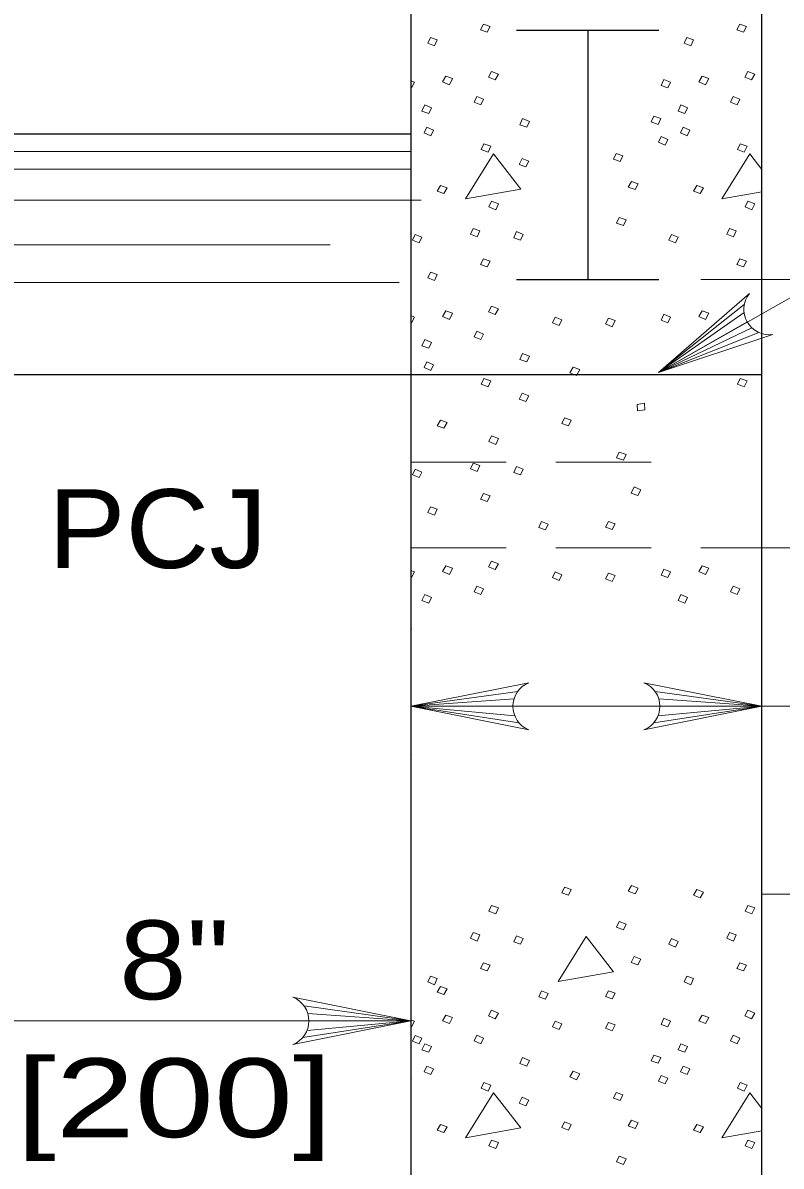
# Model space of a CAD drawing. Extents: x -1431.2 to -1397.2, y -1045.1 to -1001.1.
# Drawn here: x -1422.139 to -1420.61, y -1041.7 to -1039.396 of the extents above; entities that cross this region are included whole.
import ezdxf
from ezdxf.enums import TextEntityAlignment as Align

# ---------------------------------------------------------------- set-up
doc = ezdxf.new("R2010")
doc.units = 0
doc.header["$LTSCALE"] = 0.064
doc.linetypes.add('MEDIUM_DASHED', pattern=[4.5, 3, -1.5])
doc.layers.add('1', color=7, linetype='Continuous', lineweight=13)

msp = doc.modelspace()

# ---------------------------------------------------------------- linework, layer by layer
at = {"layer": '1', "lineweight": 25}
for p, q in [((-1420.649, -1043.61933), (-1420.649, -1038.68067)), ((-1421.35642, -1038.98608), (-1421.35642, -1040.11325)), ((-1421.1435, -1039.41017), (-1420.85692, -1039.41017)), ((-1421.00017, -1039.41017), (-1421.00017, -1039.91325)), ((-1422.38333, -1039.61925), (-1421.35642, -1039.61925)), ((-1421.1435, -1039.91325), (-1420.85692, -1039.91325)), ((-1421.35642, -1040.10408), (-1421.35642, -1042.24275))]:
    msp.add_line(p, q, dxfattribs=at)
at = {"layer": '1'}
for p, q in [((-1422.38333, -1039.65508), (-1421.61217, -1039.65508)), ((-1421.54975, -1039.65508), (-1421.7975, -1039.65508)), ((-1421.71883, -1039.65508), (-1421.35642, -1039.65508)), ((-1420.649, -1039.69142), (-1420.67358, -1039.65983)), ((-1422.24483, -1039.69092), (-1421.98408, -1039.69092)), ((-1421.79125, -1039.69092), (-1422.1705, -1039.69092)), ((-1421.97225, -1039.69092), (-1421.35642, -1039.69092)), ((-1422.28817, -1039.75308), (-1421.52967, -1039.75308)), ((-1421.33575, -1039.75308), (-1421.87775, -1039.75308)), ((-1421.71658, -1039.75308), (-1421.35642, -1039.75308)), ((-1422.23358, -1039.84283), (-1421.99242, -1039.84283)), ((-1421.75308, -1039.84283), (-1422.18017, -1039.84283)), ((-1421.8625, -1039.84283), (-1421.51908, -1039.84283)), ((-1421.37983, -1039.91908), (-1422.25742, -1039.91908)), ((-1422.01417, -1039.91908), (-1421.77283, -1039.91908)), ((-1421.71658, -1039.91908), (-1421.49108, -1039.91908)), ((-1420.77192, -1039.91325), (-1415.55833, -1039.91325)), ((-1420.68458, -1039.9635), (-1420.85742, -1040.10017)), ((-1420.68483, -1039.97967), (-1420.85742, -1040.10017)), ((-1420.67858, -1039.99842), (-1420.85742, -1040.10017)), ((-1420.66917, -1040.0105), (-1420.85742, -1040.10017)), ((-1420.65542, -1040.01983), (-1420.85742, -1040.10017)), ((-1420.734, -1040.10408), (-1421.74733, -1040.10408)), ((-1421.14117, -1040.74292), (-1421.35642, -1040.773)), ((-1421.14842, -1040.75775), (-1421.35642, -1040.773)), ((-1420.86425, -1040.74292), (-1420.649, -1040.773)), ((-1420.857, -1040.75775), (-1420.649, -1040.773)), ((-1421.35642, -1040.773), (-1419.82525, -1040.773)), ((-1421.15067, -1040.773), (-1421.35642, -1040.773)), ((-1421.14683, -1040.79233), (-1421.35642, -1040.773)), ((-1421.13867, -1040.80625), (-1421.35642, -1040.773)), ((-1420.86683, -1040.80625), (-1420.649, -1040.773)), ((-1420.85858, -1040.79233), (-1420.649, -1040.773)), ((-1420.85475, -1040.773), (-1420.649, -1040.773)), ((-1419.9465, -1041.15183), (-1420.649, -1041.15183)), ((-1421.57158, -1041.37675), (-1421.35642, -1041.40692)), ((-1421.56433, -1041.39167), (-1421.35642, -1041.40692)), ((-1421.57417, -1041.44017), (-1421.35642, -1041.40692)), ((-1421.56592, -1041.42625), (-1421.35642, -1041.40692)), ((-1421.56208, -1041.40692), (-1421.35642, -1041.40692)), ((-1420.649, -1041.58333), (-1420.67358, -1041.55175))]:
    msp.add_line(p, q, dxfattribs=at)
at = {"layer": '1', "linetype": 'MEDIUM_DASHED'}
for p, q in [((-1421.35642, -1040.28092), (-1420.856, -1040.28092)), ((-1421.35642, -1040.45358), (-1419.54317, -1040.45358))]:
    msp.add_line(p, q, dxfattribs=at)
at = {"layer": '1'}
for points in [[(-1421.21008, -1039.39808), (-1421.19642, -1039.40292), (-1421.20283, -1039.41433), (-1421.21642, -1039.4095)], [(-1420.6935, -1039.39808), (-1420.67992, -1039.40292), (-1420.68625, -1039.41433), (-1420.69983, -1039.4095)], [(-1421.317, -1039.425), (-1421.30342, -1039.42983), (-1421.30883, -1039.44208), (-1421.32242, -1039.43642)], [(-1420.80042, -1039.425), (-1420.78683, -1039.42983), (-1420.79233, -1039.44208), (-1420.80592, -1039.43642)], [(-1421.19375, -1039.4935), (-1421.18017, -1039.49917), (-1421.1865, -1039.51058), (-1421.20008, -1039.50492)], [(-1420.67725, -1039.4935), (-1420.66358, -1039.49917), (-1420.67, -1039.51058), (-1420.68358, -1039.50492)], [(-1421.28617, -1039.50325), (-1421.27258, -1039.50817), (-1421.27892, -1039.52042), (-1421.2925, -1039.51467)], [(-1420.84667, -1039.50975), (-1420.83308, -1039.5155), (-1420.8385, -1039.52692), (-1420.85208, -1039.522)], [(-1420.76967, -1039.50325), (-1420.75608, -1039.50817), (-1420.76242, -1039.52042), (-1420.776, -1039.51467)], [(-1421.32875, -1039.56117), (-1421.31517, -1039.56683), (-1421.32058, -1039.57825), (-1421.33417, -1039.57342)], [(-1421.22367, -1039.544), (-1421.21008, -1039.54975), (-1421.2155, -1039.56117), (-1421.22908, -1039.55542)], [(-1420.81225, -1039.56117), (-1420.79867, -1039.56683), (-1420.80408, -1039.57825), (-1420.81767, -1039.57342)], [(-1420.70708, -1039.544), (-1420.6935, -1039.54975), (-1420.699, -1039.56117), (-1420.71258, -1039.55542)], [(-1420.86658, -1039.584), (-1420.853, -1039.58883), (-1420.85842, -1039.60033), (-1420.872, -1039.59542)], [(-1421.32425, -1039.606), (-1421.31067, -1039.61175), (-1421.31608, -1039.62317), (-1421.32967, -1039.61742)], [(-1421.13125, -1039.58883), (-1421.11758, -1039.59458), (-1421.12308, -1039.606), (-1421.13667, -1039.60108)], [(-1420.80767, -1039.606), (-1420.79408, -1039.61175), (-1420.79958, -1039.62317), (-1420.81317, -1039.61742)], [(-1420.85208, -1039.62475), (-1420.8385, -1039.6305), (-1420.844, -1039.64192), (-1420.85758, -1039.63617)], [(-1421.20917, -1039.63942), (-1421.19558, -1039.64433), (-1421.201, -1039.65658), (-1421.21458, -1039.65083)], [(-1420.69258, -1039.63942), (-1420.679, -1039.64433), (-1420.6845, -1039.65658), (-1420.69808, -1039.65083)], [(-1421.19008, -1039.65983), (-1421.24633, -1039.75033), (-1421.13483, -1039.73075)], [(-1421.13208, -1039.66883), (-1421.1185, -1039.6745), (-1421.12483, -1039.68592), (-1421.1385, -1039.681)], [(-1420.94275, -1039.659), (-1420.92917, -1039.66392), (-1420.93458, -1039.67533), (-1420.94817, -1039.67042)], [(-1421.29708, -1039.72342), (-1421.28342, -1039.72833), (-1421.28983, -1039.73975), (-1421.30342, -1039.73483)], [(-1420.91192, -1039.71525), (-1420.89833, -1039.72017), (-1420.90467, -1039.73158), (-1420.91825, -1039.72667)], [(-1420.7805, -1039.72342), (-1420.76692, -1039.72833), (-1420.77325, -1039.73975), (-1420.78683, -1039.73483)], [(-1421.19375, -1039.75525), (-1421.18017, -1039.76017), (-1421.18558, -1039.77233), (-1421.19917, -1039.76667)], [(-1420.67725, -1039.75525), (-1420.66358, -1039.76017), (-1420.66908, -1039.77233), (-1420.68267, -1039.76667)], [(-1420.93642, -1039.78783), (-1420.92275, -1039.79275), (-1420.92825, -1039.80417), (-1420.94183, -1039.79925)], [(-1421.23092, -1039.80983), (-1421.21733, -1039.81475), (-1421.22275, -1039.827), (-1421.23633, -1039.82133)], [(-1421.14392, -1039.81642), (-1421.13033, -1039.82208), (-1421.13575, -1039.8335), (-1421.14933, -1039.82867)], [(-1420.71433, -1039.80983), (-1420.70075, -1039.81475), (-1420.70625, -1039.827), (-1420.71983, -1039.82133)], [(-1421.34783, -1039.82208), (-1421.33417, -1039.82783), (-1421.33967, -1039.83925), (-1421.35325, -1039.8335)], [(-1420.83125, -1039.82208), (-1420.81767, -1039.82783), (-1420.82308, -1039.83925), (-1420.83667, -1039.8335)], [(-1421.21008, -1039.871), (-1421.19642, -1039.87592), (-1421.20283, -1039.88733), (-1421.21642, -1039.88242)], [(-1420.6935, -1039.871), (-1420.67992, -1039.87592), (-1420.68625, -1039.88733), (-1420.69983, -1039.88242)], [(-1421.317, -1039.89792), (-1421.30342, -1039.90283), (-1421.30883, -1039.91508), (-1421.32242, -1039.90933)], [(-1421.28617, -1039.97625), (-1421.27258, -1039.98108), (-1421.27892, -1039.99333), (-1421.2925, -1039.98767)], [(-1421.19375, -1039.96642), (-1421.18017, -1039.97217), (-1421.1865, -1039.98358), (-1421.20008, -1039.97783)], [(-1420.76967, -1039.97625), (-1420.75608, -1039.98108), (-1420.76242, -1039.99333), (-1420.776, -1039.98767)], [(-1421.066, -1039.9885), (-1421.05242, -1039.99417), (-1421.05783, -1040.00558), (-1421.07142, -1039.99992)], [(-1420.95817, -1039.99092), (-1420.94458, -1039.99583), (-1420.95092, -1040.008), (-1420.9645, -1040.00233)], [(-1420.84667, -1039.98275), (-1420.83308, -1039.9885), (-1420.8385, -1039.99992), (-1420.85208, -1039.995)], [(-1421.22367, -1040.017), (-1421.21008, -1040.02275), (-1421.2155, -1040.03408), (-1421.22908, -1040.02842)], [(-1421.32875, -1040.03408), (-1421.31517, -1040.03983), (-1421.32058, -1040.05125), (-1421.33417, -1040.04633)], [(-1421.13125, -1040.06183), (-1421.11758, -1040.06758), (-1421.12308, -1040.079), (-1421.13667, -1040.07408)], [(-1421.32425, -1040.079), (-1421.31067, -1040.08467), (-1421.31608, -1040.09608), (-1421.32967, -1040.09042)], [(-1421.02975, -1040.08958), (-1421.01617, -1040.0945), (-1421.0225, -1040.10667), (-1421.03608, -1040.101)], [(-1421.20917, -1040.11242), (-1421.19558, -1040.11733), (-1421.201, -1040.1295), (-1421.21458, -1040.12383)], [(-1420.69258, -1040.11242), (-1420.679, -1040.11733), (-1420.6845, -1040.1295), (-1420.69808, -1040.12383)], [(-1421.13208, -1040.14175), (-1421.1185, -1040.1475), (-1421.12483, -1040.15892), (-1421.1385, -1040.154)], [(-1420.885, -1040.17525), (-1420.89958, -1040.17775), (-1420.90033, -1040.16467), (-1420.88583, -1040.16217)], [(-1421.29708, -1040.19642), (-1421.28342, -1040.20133), (-1421.28983, -1040.21275), (-1421.30342, -1040.20783)], [(-1421.04692, -1040.1915), (-1421.03333, -1040.19642), (-1421.03875, -1040.20783), (-1421.05242, -1040.20292)], [(-1421.19375, -1040.22817), (-1421.18017, -1040.23308), (-1421.18558, -1040.24533), (-1421.19917, -1040.23967)], [(-1420.93642, -1040.26083), (-1420.92275, -1040.26575), (-1420.92825, -1040.27717), (-1420.94183, -1040.27225)], [(-1421.34783, -1040.29508), (-1421.33417, -1040.30083), (-1421.33967, -1040.31217), (-1421.35325, -1040.3065)], [(-1421.23092, -1040.28283), (-1421.21733, -1040.28775), (-1421.22275, -1040.3), (-1421.23633, -1040.29425)], [(-1421.14392, -1040.28942), (-1421.13033, -1040.29508), (-1421.13575, -1040.3065), (-1421.14933, -1040.30158)], [(-1421.21008, -1040.344), (-1421.19642, -1040.34892), (-1421.20283, -1040.36033), (-1421.21642, -1040.35542)], [(-1420.9065, -1040.331), (-1420.89292, -1040.33667), (-1420.89925, -1040.34808), (-1420.91283, -1040.34317)], [(-1421.317, -1040.37092), (-1421.30342, -1040.37583), (-1421.30883, -1040.38808), (-1421.32242, -1040.38233)], [(-1421.09317, -1040.40025), (-1421.07958, -1040.406), (-1421.085, -1040.41742), (-1421.09858, -1040.4125)], [(-1420.95817, -1040.40025), (-1420.94458, -1040.40517), (-1420.95092, -1040.41658), (-1420.9645, -1040.41167)], [(-1421.19375, -1040.48017), (-1421.18017, -1040.48592), (-1421.1865, -1040.49733), (-1421.20008, -1040.49158)], [(-1421.28617, -1040.48992), (-1421.27258, -1040.49483), (-1421.27892, -1040.50708), (-1421.2925, -1040.50142)], [(-1421.066, -1040.50217), (-1421.05242, -1040.50792), (-1421.05783, -1040.51933), (-1421.07142, -1040.51358)], [(-1420.95817, -1040.50467), (-1420.94458, -1040.5095), (-1420.95092, -1040.52175), (-1420.9645, -1040.51608)], [(-1420.84667, -1040.4965), (-1420.83308, -1040.50217), (-1420.8385, -1040.51358), (-1420.85208, -1040.50875)], [(-1420.76967, -1040.48992), (-1420.75608, -1040.49483), (-1420.76242, -1040.50708), (-1420.776, -1040.50142)], [(-1421.22367, -1040.53075), (-1421.21008, -1040.53642), (-1421.2155, -1040.54783), (-1421.22908, -1040.54217)], [(-1420.70708, -1040.53075), (-1420.6935, -1040.53642), (-1420.699, -1040.54783), (-1420.71258, -1040.54217)], [(-1421.32875, -1040.54783), (-1421.31517, -1040.55358), (-1421.32058, -1040.565), (-1421.33417, -1040.56008)], [(-1420.81225, -1040.54783), (-1420.79867, -1040.55358), (-1420.80408, -1040.565), (-1420.81767, -1040.56008)], [(-1421.04692, -1041.1375), (-1421.03333, -1041.14233), (-1421.03875, -1041.15375), (-1421.05242, -1041.14892)], [(-1420.91192, -1041.13425), (-1420.89833, -1041.13908), (-1420.90467, -1041.1505), (-1420.91825, -1041.14567)], [(-1420.7805, -1041.14233), (-1420.76692, -1041.14725), (-1420.77325, -1041.15867), (-1420.78683, -1041.15375)], [(-1421.19375, -1041.17417), (-1421.18017, -1041.17908), (-1421.18558, -1041.19133), (-1421.19917, -1041.18558)], [(-1420.67725, -1041.17417), (-1420.66358, -1041.17908), (-1420.66908, -1041.19133), (-1420.68267, -1041.18558)], [(-1420.93642, -1041.20675), (-1420.92275, -1041.21167), (-1420.92825, -1041.22308), (-1420.94183, -1041.21817)], [(-1421.23092, -1041.22883), (-1421.21733, -1041.23367), (-1421.22275, -1041.24592), (-1421.23633, -1041.24025)], [(-1421.14392, -1041.23533), (-1421.13033, -1041.241), (-1421.13575, -1041.25242), (-1421.14933, -1041.24758)], [(-1421.00342, -1041.237), (-1421.05967, -1041.3275), (-1420.94817, -1041.30792)], [(-1420.83125, -1041.241), (-1420.81767, -1041.24675), (-1420.82308, -1041.25817), (-1420.83667, -1041.25242)], [(-1420.71433, -1041.22883), (-1420.70075, -1041.23367), (-1420.70625, -1041.24592), (-1420.71983, -1041.24025)], [(-1421.21008, -1041.29), (-1421.19642, -1041.29483), (-1421.20283, -1041.30625), (-1421.21642, -1041.30142)], [(-1420.9065, -1041.27692), (-1420.89292, -1041.28267), (-1420.89925, -1041.29408), (-1420.91283, -1041.28917)], [(-1420.6935, -1041.29), (-1420.67992, -1041.29483), (-1420.68625, -1041.30625), (-1420.69983, -1041.30142)], [(-1421.317, -1041.31692), (-1421.30342, -1041.32175), (-1421.30883, -1041.334), (-1421.32242, -1041.32833)], [(-1421.29708, -1041.33742), (-1421.28342, -1041.34233), (-1421.28983, -1041.35375), (-1421.30342, -1041.34883)], [(-1420.80042, -1041.31692), (-1420.78683, -1041.32175), (-1420.79233, -1041.334), (-1420.80592, -1041.32833)], [(-1421.09317, -1041.34625), (-1421.07958, -1041.35192), (-1421.085, -1041.36333), (-1421.09858, -1041.3585)], [(-1420.95817, -1041.34625), (-1420.94458, -1041.35108), (-1420.95092, -1041.36258), (-1420.9645, -1041.35767)], [(-1421.28617, -1041.39517), (-1421.27258, -1041.40008), (-1421.27892, -1041.41225), (-1421.2925, -1041.40658)], [(-1421.19375, -1041.38542), (-1421.18017, -1041.39108), (-1421.1865, -1041.4025), (-1421.20008, -1041.39683)], [(-1420.84667, -1041.40167), (-1420.83308, -1041.40742), (-1420.8385, -1041.41883), (-1420.85208, -1041.41392)], [(-1420.76967, -1041.39517), (-1420.75608, -1041.40008), (-1420.76242, -1041.41225), (-1420.776, -1041.40658)], [(-1420.67725, -1041.38542), (-1420.66358, -1041.39108), (-1420.67, -1041.4025), (-1420.68358, -1041.39683)], [(-1421.066, -1041.40742), (-1421.05242, -1041.41308), (-1421.05783, -1041.4245), (-1421.07142, -1041.41883)], [(-1420.95817, -1041.40983), (-1420.94458, -1041.41475), (-1420.95092, -1041.427), (-1420.9645, -1041.42125)], [(-1421.34783, -1041.43608), (-1421.33417, -1041.44183), (-1421.33967, -1041.45325), (-1421.35325, -1041.4475)], [(-1421.22367, -1041.43592), (-1421.21008, -1041.44167), (-1421.2155, -1041.45308), (-1421.22908, -1041.44733)], [(-1420.70708, -1041.43592), (-1420.6935, -1041.44167), (-1420.699, -1041.45308), (-1420.71258, -1041.44733)], [(-1421.32875, -1041.45308), (-1421.31517, -1041.45875), (-1421.32058, -1041.47017), (-1421.33417, -1041.46533)], [(-1420.86658, -1041.47592), (-1420.853, -1041.48075), (-1420.85842, -1041.49217), (-1420.872, -1041.48733)], [(-1420.81225, -1041.45308), (-1420.79867, -1041.45875), (-1420.80408, -1041.47017), (-1420.81767, -1041.46533)], [(-1421.32425, -1041.49792), (-1421.31067, -1041.50358), (-1421.31608, -1041.515), (-1421.32967, -1041.50933)], [(-1421.13125, -1041.48075), (-1421.11758, -1041.4865), (-1421.12308, -1041.49792), (-1421.13667, -1041.493)], [(-1420.80767, -1041.49792), (-1420.79408, -1041.50358), (-1420.79958, -1041.515), (-1420.81317, -1041.50933)], [(-1421.02975, -1041.5085), (-1421.01617, -1041.51342), (-1421.0225, -1041.52567), (-1421.03608, -1041.51992)], [(-1420.85208, -1041.51667), (-1420.8385, -1041.52242), (-1420.844, -1041.53383), (-1420.85758, -1041.52808)], [(-1421.20917, -1041.53133), (-1421.19558, -1041.53625), (-1421.201, -1041.5485), (-1421.21458, -1041.54275)], [(-1420.69258, -1041.53133), (-1420.679, -1041.53625), (-1420.6845, -1041.5485), (-1420.69808, -1041.54275)], [(-1421.19008, -1041.55175), (-1421.24633, -1041.64225), (-1421.13483, -1041.62267)], [(-1421.13208, -1041.56067), (-1421.1185, -1041.56642), (-1421.12483, -1041.57783), (-1421.1385, -1041.57292)], [(-1420.94275, -1041.55092), (-1420.92917, -1041.55583), (-1420.93458, -1041.56725), (-1420.94817, -1041.56233)], [(-1421.04692, -1041.61042), (-1421.03333, -1041.61533), (-1421.03875, -1041.62675), (-1421.05242, -1041.62183)], [(-1420.91192, -1041.60717), (-1420.89833, -1041.61208), (-1420.90467, -1041.6235), (-1420.91825, -1041.61858)], [(-1421.29708, -1041.61533), (-1421.28342, -1041.62025), (-1421.28983, -1041.63167), (-1421.30342, -1041.62675)], [(-1420.7805, -1041.61533), (-1420.76692, -1041.62025), (-1420.77325, -1041.63167), (-1420.78683, -1041.62675)], [(-1421.19375, -1041.64717), (-1421.18017, -1041.652), (-1421.18558, -1041.66425), (-1421.19917, -1041.65858)], [(-1420.67725, -1041.64717), (-1420.66358, -1041.652), (-1420.66908, -1041.66425), (-1420.68267, -1041.65858)], [(-1420.93642, -1041.67975), (-1420.92275, -1041.68467), (-1420.92825, -1041.69608), (-1420.94183, -1041.69117)]]:
    msp.add_lwpolyline(points, close=True, dxfattribs=at)
for points in [[(-1421.35642, -1039.51267), (-1421.34958, -1039.5155), (-1421.355, -1039.52692), (-1421.35642, -1039.52642)], [(-1421.35642, -1039.62992), (-1421.355, -1039.6305), (-1421.35642, -1039.63333)], [(-1420.67358, -1039.65983), (-1420.72975, -1039.75033), (-1420.649, -1039.73617)], [(-1420.85742, -1040.10017), (-1420.16867, -1039.71008), (-1419.82525, -1039.71008)], [(-1420.67425, -1039.94125), (-1420.85742, -1040.10017), (-1420.62725, -1040.02383)], [(-1421.35642, -1039.98558), (-1421.34958, -1039.9885), (-1421.355, -1039.99992), (-1421.35642, -1039.99942)], [(-1421.35642, -1040.10292), (-1421.355, -1040.10342), (-1421.35642, -1040.10633)], [(-1421.35642, -1040.49933), (-1421.34958, -1040.50217), (-1421.355, -1040.51358), (-1421.35642, -1040.51308)], [(-1421.35642, -1040.61658), (-1421.355, -1040.61717), (-1421.35642, -1040.62)], [(-1421.11867, -1040.82058), (-1421.35642, -1040.773), (-1421.11867, -1040.72542)], [(-1420.88675, -1040.82058), (-1420.649, -1040.773), (-1420.88675, -1040.72542)], [(-1421.35642, -1040.87092), (-1421.355, -1040.8715), (-1421.35642, -1040.87433)], [(-1421.59417, -1041.45442), (-1421.35642, -1041.40692), (-1421.59417, -1041.35933)], [(-1421.35642, -1041.4045), (-1421.34958, -1041.40742), (-1421.355, -1041.41883), (-1421.35642, -1041.41833)], [(-1422.38333, -1041.40692), (-1421.92633, -1041.40692), (-1421.35642, -1041.40692)], [(-1421.35642, -1041.52183), (-1421.355, -1041.52242), (-1421.35642, -1041.52525)], [(-1420.67358, -1041.55175), (-1420.72975, -1041.64225), (-1420.649, -1041.62808)]]:
    msp.add_lwpolyline(points, dxfattribs=at)
at = {"layer": '1', "lineweight": 25}
msp.add_lwpolyline([(-1423.1035, -1040.10408), (-1422.38333, -1040.10408), (-1420.649, -1040.10408)], dxfattribs=at)
at = {"layer": '1'}
for centre, start, end in [((-1420.63406, -1039.9731), 141.73751, 277.56363), ((-1421.09946, -1040.77294), 112.08782, 247.91395), ((-1420.90597, -1040.77294), 292.08605, 67.91218), ((-1421.61333, -1041.40683), 292.08605, 67.91218)]:
    msp.add_arc(centre, 0.05131, start, end, dxfattribs=at)

# ---------------------------------------------------------------- texts
at = {"layer": '1', "width": 1.1}
msp.add_text('PCJ', height=0.1588, dxfattribs=at).set_placement((-1422.0875, -1040.49433))
at = {"layer": '1'}
for s, width, p in [('8"', 1.15, (-1421.83333, -1041.36333)), ('[200]', 1.35, (-1421.83333, -1041.64117))]:
    msp.add_text(s, height=0.1588, dxfattribs=dict(at, width=width)).set_placement(p, align=Align.CENTER)

doc.saveas('drawing.dxf')
